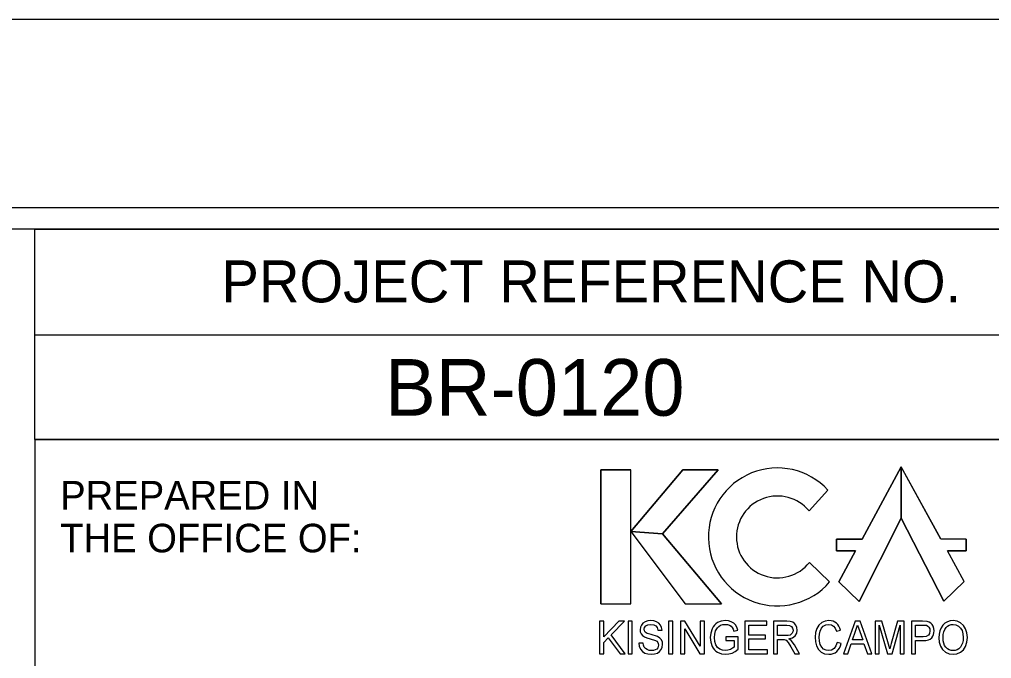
# Model space of a CAD drawing. Extents: x 406996 to 407670, y -135414 to -134930.
# Drawn here: x 407582.24 to 407628.52, y -134960.54 to -134930.09 of the extents above; entities that cross this region are included whole.
import ezdxf

# ---------------------------------------------------------------- set-up
doc = ezdxf.new("R2010")
doc.units = 0
for name, color, linetype in [('Default', 7, 'Continuous'), ('Sheet Cutting Line CELL', 7, 'Continuous'), ('Sheet Data Field CELL', 7, 'Continuous'), ('Sheet Plot Border Inside CELL', 7, 'Continuous'), ('Sheet Plot Border Outside CELL', 7, 'Continuous'), ('Sheet Summary Combination CELL', 7, 'Continuous'), ('Sheet Typical CELL', 7, 'Continuous')]:
    doc.layers.add(name, color=color, linetype=linetype)

msp = doc.modelspace()

# ---------------------------------------------------------------- linework, layer by layer
at = {"layer": 'Default'}
for p, q in [((407609.928, -134957.934), (407609.928, -134951.554)), ((407609.928, -134951.554), (407611.353, -134951.554)), ((407611.353, -134951.554), (407609.928, -134951.554)), ((407611.353, -134951.554), (407609.928, -134951.554)), ((407609.928, -134951.554), (407609.928, -134957.934)), ((407611.353, -134957.934), (407611.353, -134951.554)), ((407611.353, -134954.493), (407613.82, -134951.554)), ((407611.353, -134954.493), (407611.353, -134951.554)), ((407613.82, -134951.554), (407611.353, -134954.493)), ((407611.353, -134954.493), (407611.353, -134951.554)), ((407612.858, -134954.606), (407615.511, -134951.554)), ((407612.858, -134954.606), (407615.511, -134951.554)), ((407613.82, -134951.554), (407615.511, -134951.554)), ((407615.511, -134951.554), (407613.82, -134951.554)), ((407622.358, -134954.849), (407624.225, -134951.405)), ((407624.225, -134951.405), (407622.358, -134954.849)), ((407624.225, -134951.405), (407622.358, -134954.849)), ((407624.225, -134953.849), (407624.225, -134951.405)), ((407626.107, -134954.841), (407624.225, -134951.405)), ((407624.225, -134953.849), (407624.225, -134951.405)), ((407624.225, -134953.849), (407624.225, -134951.405)), ((407626.104, -134954.849), (407624.225, -134951.405)), ((407624.225, -134951.405), (407624.225, -134953.849)), ((407620.736, -134952.51), (407619.833, -134953.506)), ((407619.833, -134953.506), (407620.736, -134952.51)), ((407622.221, -134957.826), (407624.225, -134953.849)), ((407622.221, -134957.826), (407624.225, -134953.849)), ((407626.251, -134957.805), (407624.225, -134953.849)), ((407624.225, -134953.849), (407626.251, -134957.805)), ((407611.353, -134954.493), (407613.938, -134957.934)), ((407611.353, -134957.934), (407611.353, -134954.493)), ((407612.858, -134954.606), (407611.353, -134954.493)), ((407611.353, -134954.493), (407613.938, -134957.934)), ((407611.353, -134954.493), (407612.858, -134954.606)), ((407611.353, -134957.934), (407611.353, -134954.493)), ((407612.858, -134954.606), (407615.659, -134957.934)), ((407621.141, -134954.849), (407621.141, -134955.413)), ((407622.358, -134954.849), (407621.141, -134954.849)), ((407622.358, -134954.849), (407621.141, -134954.849)), ((407621.141, -134954.849), (407621.141, -134955.413)), ((407622.358, -134954.849), (407621.141, -134954.849)), ((407621.141, -134954.849), (407621.141, -134955.413)), ((407627.32, -134954.849), (407626.104, -134954.849)), ((407627.32, -134954.849), (407626.104, -134954.849)), ((407627.32, -134954.849), (407627.32, -134955.413)), ((407627.32, -134955.413), (407627.32, -134954.849)), ((407622.052, -134955.413), (407621.141, -134955.413)), ((407621.141, -134955.413), (407622.052, -134955.413)), ((407621.141, -134955.413), (407622.052, -134955.413)), ((407621.251, -134956.891), (407622.052, -134955.413)), ((407622.052, -134955.413), (407621.251, -134956.891)), ((407622.052, -134955.413), (407621.251, -134956.891)), ((407627.32, -134955.413), (407626.421, -134955.413)), ((407627.22, -134956.871), (407626.421, -134955.413)), ((407627.22, -134956.871), (407626.421, -134955.413)), ((407626.421, -134955.413), (407627.32, -134955.413)), ((407619.853, -134955.961), (407620.815, -134956.892)), ((407620.815, -134956.892), (407619.853, -134955.961)), ((407621.251, -134956.891), (407622.221, -134957.826)), ((407621.251, -134956.891), (407622.221, -134957.826)), ((407627.22, -134956.871), (407626.251, -134957.805)), ((407626.251, -134957.805), (407627.22, -134956.871)), ((407609.928, -134957.934), (407611.353, -134957.934)), ((407609.928, -134957.934), (407611.353, -134957.934)), ((407613.938, -134957.934), (407615.659, -134957.934))]:
    msp.add_line(p, q, dxfattribs=at)
for points in [[(407609.928, -134951.554), (407609.928, -134957.934), (407611.353, -134957.934), (407611.353, -134951.554)], [(407611.353, -134954.493), (407613.82, -134951.554), (407615.511, -134951.554), (407612.858, -134954.606)], [(407624.225, -134953.849), (407622.221, -134957.826), (407621.251, -134956.891), (407622.052, -134955.413), (407621.141, -134955.413), (407621.141, -134954.849), (407622.358, -134954.849), (407624.225, -134951.405)], [(407624.225, -134951.405), (407624.225, -134953.849), (407626.251, -134957.805), (407627.22, -134956.871), (407626.421, -134955.413), (407627.32, -134955.413), (407627.32, -134954.849), (407626.104, -134954.849)], [(407611.353, -134954.493), (407613.938, -134957.934), (407615.659, -134957.934), (407612.858, -134954.606)], [(407609.861, -134960.309), (407610.059, -134960.309), (407610.059, -134959.774), (407610.278, -134959.551), (407610.837, -134960.309), (407611.079, -134960.309), (407610.417, -134959.41), (407611.051, -134958.765), (407610.778, -134958.765), (407610.059, -134959.498), (407610.059, -134958.765), (407609.861, -134958.765)], [(407611.221, -134960.309), (407611.42, -134960.309), (407611.42, -134958.765), (407611.221, -134958.765)], [(407611.731, -134959.804), (407611.753, -134959.954), (407611.809, -134960.088), (407611.898, -134960.198), (407612.015, -134960.276), (407612.161, -134960.323), (407612.339, -134960.338), (407612.483, -134960.323), (407612.613, -134960.278), (407612.72, -134960.205), (407612.8, -134960.108), (407612.849, -134959.995), (407612.865, -134959.875), (407612.85, -134959.758), (407612.806, -134959.655), (407612.73, -134959.567), (407612.622, -134959.497), (407612.315, -134959.397), (407612.135, -134959.341), (407612.04, -134959.286), (407612, -134959.225), (407611.987, -134959.148), (407612.005, -134959.058), (407612.062, -134958.982), (407612.16, -134958.931), (407612.303, -134958.914), (407612.442, -134958.931), (407612.543, -134958.981), (407612.607, -134959.065), (407612.638, -134959.181), (407612.837, -134959.181), (407612.816, -134959.057), (407612.766, -134958.946), (407612.686, -134958.855), (407612.578, -134958.789), (407612.446, -134958.749), (407612.295, -134958.735), (407612.156, -134958.749), (407612.031, -134958.788), (407611.926, -134958.854), (407611.85, -134958.944), (407611.804, -134959.05), (407611.788, -134959.164), (407611.801, -134959.266), (407611.84, -134959.357), (407611.906, -134959.436), (407612, -134959.502), (407612.109, -134959.549), (407612.272, -134959.599), (407612.517, -134959.675), (407612.59, -134959.717), (407612.635, -134959.768), (407612.659, -134959.828), (407612.667, -134959.897), (407612.657, -134959.967), (407612.628, -134960.031), (407612.58, -134960.085), (407612.511, -134960.126), (407612.427, -134960.152), (407612.33, -134960.16), (407612.22, -134960.149), (407612.122, -134960.114), (407612.042, -134960.062), (407611.986, -134959.994), (407611.949, -134959.91), (407611.93, -134959.804)], [(407613.149, -134960.309), (407613.347, -134960.309), (407613.347, -134958.765), (407613.149, -134958.765)], [(407613.716, -134960.309), (407613.914, -134960.309), (407613.914, -134959.127), (407614.638, -134960.309), (407614.849, -134960.309), (407614.849, -134958.765), (407614.651, -134958.765), (407614.651, -134959.946), (407613.927, -134958.765), (407613.716, -134958.765)], [(407615.869, -134959.685), (407616.266, -134959.685), (407616.266, -134959.991), (407616.191, -134960.05), (407616.089, -134960.106), (407615.972, -134960.147), (407615.851, -134960.16), (407615.715, -134960.144), (407615.586, -134960.093), (407615.476, -134960.007), (407615.396, -134959.884), (407615.346, -134959.728), (407615.331, -134959.536), (407615.344, -134959.374), (407615.385, -134959.223), (407615.474, -134959.069), (407615.541, -134959.006), (407615.626, -134958.957), (407615.728, -134958.925), (407615.849, -134958.914), (407615.951, -134958.924), (407616.044, -134958.953), (407616.122, -134959), (407616.18, -134959.059), (407616.223, -134959.137), (407616.259, -134959.24), (407616.441, -134959.19), (407616.395, -134959.05), (407616.332, -134958.939), (407616.247, -134958.854), (407616.134, -134958.789), (407616.001, -134958.749), (407615.852, -134958.735), (407615.65, -134958.76), (407615.473, -134958.83), (407615.395, -134958.885), (407615.327, -134958.951), (407615.268, -134959.03), (407615.22, -134959.122), (407615.154, -134959.326), (407615.132, -134959.544), (407615.154, -134959.762), (407615.22, -134959.958), (407615.269, -134960.045), (407615.33, -134960.121), (407615.401, -134960.187), (407615.482, -134960.241), (407615.665, -134960.314), (407615.868, -134960.338), (407616.023, -134960.323), (407616.174, -134960.277), (407616.321, -134960.2), (407616.464, -134960.092), (407616.464, -134959.507), (407615.869, -134959.507)], [(407616.776, -134960.309), (407617.852, -134960.309), (407617.852, -134960.131), (407616.974, -134960.131), (407616.974, -134959.596), (407617.767, -134959.596), (407617.767, -134959.418), (407616.974, -134959.418), (407616.974, -134958.943), (407617.824, -134958.943), (407617.824, -134958.765), (407616.776, -134958.765)], [(407621.168, -134959.768), (407621.113, -134959.939), (407621.024, -134960.062), (407620.906, -134960.136), (407620.764, -134960.16), (407620.642, -134960.142), (407620.529, -134960.088), (407620.435, -134959.997), (407620.369, -134959.868), (407620.331, -134959.709), (407620.318, -134959.524), (407620.329, -134959.374), (407620.361, -134959.228), (407620.419, -134959.099), (407620.51, -134958.999), (407620.629, -134958.935), (407620.774, -134958.914), (407620.899, -134958.933), (407621.001, -134958.991), (407621.081, -134959.091), (407621.14, -134959.236), (407621.338, -134959.189), (407621.304, -134959.087), (407621.259, -134958.997), (407621.203, -134958.92), (407621.137, -134958.855), (407621.061, -134958.803), (407620.977, -134958.765), (407620.884, -134958.743), (407620.783, -134958.735), (407620.605, -134958.759), (407620.442, -134958.829), (407620.305, -134958.945), (407620.203, -134959.103), (407620.14, -134959.299), (407620.12, -134959.525), (407620.138, -134959.741), (407620.194, -134959.941), (407620.286, -134960.112), (407620.412, -134960.236), (407620.575, -134960.313), (407620.782, -134960.338), (407620.888, -134960.33), (407620.986, -134960.305), (407621.075, -134960.264), (407621.155, -134960.205), (407621.225, -134960.132), (407621.284, -134960.042), (407621.331, -134959.939), (407621.366, -134959.819)], [(407622.982, -134960.309), (407623.18, -134960.309), (407623.18, -134958.943), (407623.568, -134960.309), (407623.785, -134960.309), (407624.172, -134958.943), (407624.172, -134960.309), (407624.37, -134960.309), (407624.37, -134958.765), (407624.052, -134958.765), (407623.744, -134959.83), (407623.676, -134960.075), (407623.613, -134959.849), (407623.301, -134958.765), (407622.982, -134958.765)]]:
    msp.add_lwpolyline(points, close=True, dxfattribs=at)
for points in [[(407609.928, -134951.554), (407609.928, -134957.934), (407611.353, -134957.934)], [(407621.251, -134956.891), (407622.221, -134957.826), (407624.225, -134953.849)], [(407613.938, -134957.934), (407615.659, -134957.934), (407612.858, -134954.606)], [(407618.136, -134960.309), (407618.335, -134960.309), (407618.335, -134959.626), (407618.55, -134959.626), (407618.653, -134959.632), (407618.738, -134959.667), (407618.832, -134959.768), (407618.966, -134959.983), (407619.151, -134960.309), (407619.377, -134960.309), (407619.136, -134959.882), (407618.984, -134959.676), (407618.875, -134959.596), (407619.05, -134959.546), (407619.173, -134959.455), (407619.245, -134959.331), (407619.27, -134959.181), (407619.255, -134959.061), (407619.211, -134958.952), (407619.143, -134958.864), (407619.055, -134958.806), (407618.935, -134958.776), (407618.771, -134958.765), (407618.136, -134958.765), (407618.136, -134960.309)], [(407618.335, -134959.448), (407618.335, -134958.943), (407618.778, -134958.943), (407618.91, -134958.961), (407619.001, -134959.013), (407619.054, -134959.093), (407619.071, -134959.191), (407619.062, -134959.262), (407619.035, -134959.328), (407618.99, -134959.383), (407618.93, -134959.42), (407618.846, -134959.441), (407618.734, -134959.448), (407618.335, -134959.448)], [(407621.469, -134960.309), (407621.678, -134960.309), (407621.841, -134959.834), (407622.45, -134959.834), (407622.613, -134960.309), (407622.822, -134960.309), (407622.263, -134958.765), (407622.028, -134958.765), (407621.469, -134960.309)], [(407621.901, -134959.656), (407622.048, -134959.228), (407622.146, -134958.943), (407622.251, -134959.253), (407622.39, -134959.656), (407621.901, -134959.656)], [(407624.709, -134960.309), (407624.908, -134960.309), (407624.908, -134959.685), (407625.265, -134959.685), (407625.401, -134959.677), (407625.515, -134959.652), (407625.605, -134959.609), (407625.673, -134959.549), (407625.723, -134959.476), (407625.758, -134959.396), (407625.779, -134959.309), (407625.786, -134959.214), (407625.775, -134959.103), (407625.743, -134959.002), (407625.694, -134958.917), (407625.631, -134958.852), (407625.552, -134958.808), (407625.457, -134958.78), (407625.242, -134958.765), (407624.709, -134958.765), (407624.709, -134960.309)], [(407624.908, -134959.507), (407624.908, -134958.943), (407625.26, -134958.943), (407625.43, -134958.957), (407625.494, -134958.992), (407625.544, -134959.05), (407625.577, -134959.128), (407625.588, -134959.22), (407625.569, -134959.342), (407625.514, -134959.432), (407625.414, -134959.489), (407625.264, -134959.507), (407624.908, -134959.507)], [(407626.013, -134959.557), (407626.034, -134959.756), (407626.095, -134959.944), (407626.195, -134960.108), (407626.335, -134960.233), (407626.503, -134960.312), (407626.694, -134960.338), (407626.873, -134960.315), (407627.039, -134960.243), (407627.181, -134960.125), (407627.286, -134959.961), (407627.351, -134959.763), (407627.374, -134959.54), (407627.353, -134959.319), (407627.29, -134959.124), (407627.189, -134958.961), (407627.05, -134958.838), (407626.881, -134958.761), (407626.695, -134958.735), (407626.551, -134958.749), (407626.421, -134958.79), (407626.305, -134958.859), (407626.203, -134958.954), (407626.12, -134959.074), (407626.061, -134959.214), (407626.025, -134959.376), (407626.013, -134959.557)], [(407626.212, -134959.56), (407626.221, -134959.398), (407626.247, -134959.261), (407626.292, -134959.15), (407626.354, -134959.062), (407626.429, -134958.997), (407626.511, -134958.951), (407626.599, -134958.923), (407626.695, -134958.914), (407626.828, -134958.933), (407626.947, -134958.991), (407627.045, -134959.085), (407627.117, -134959.209), (407627.161, -134959.362), (407627.175, -134959.538), (407627.166, -134959.679), (407627.141, -134959.802), (407627.098, -134959.909), (407627.039, -134959.998), (407626.966, -134960.07), (407626.884, -134960.12), (407626.793, -134960.151), (407626.693, -134960.16), (407626.594, -134960.151), (407626.503, -134960.12), (407626.421, -134960.07), (407626.349, -134960), (407626.288, -134959.913), (407626.246, -134959.81), (407626.22, -134959.693), (407626.212, -134959.56)]]:
    msp.add_lwpolyline(points, dxfattribs=at)
for radius, start, end in [(3.285, 42.8783, 319.2064), (3.285, 42.8783, 319.2064), (1.95, 39.4666, 321.4328), (1.95, 39.4666, 321.4328)]:
    msp.add_arc((407618.328, -134954.746), radius, start, end, dxfattribs=at)
at = {"layer": 'Sheet Cutting Line CELL'}
msp.add_line((407669.8, -134930.091), (406996.2, -134930.091), dxfattribs=at)
at = {"layer": 'Sheet Plot Border Inside CELL'}
msp.add_lwpolyline([(407668, -134939.071), (407001.4, -134939.071), (407001.4, -135361.111), (407668, -135361.111)], close=True, dxfattribs=at)
at = {"layer": 'Sheet Plot Border Outside CELL'}
msp.add_lwpolyline([(407669.8, -134930.091), (406996.2, -134930.091), (406996.2, -135370.091), (407669.8, -135370.091)], close=True, dxfattribs=at)
at = {"layer": 'Sheet Summary Combination CELL'}
for p, q in [((407582.98, -134945.111), (407663, -134945.111)), ((407582.98, -134950.111), (407663, -134950.111))]:
    msp.add_line(p, q, dxfattribs=at)
for points in [[(407663, -134940.091), (407063, -134940.091), (407063, -135360.091), (407663, -135360.091)], [(407582.98, -134940.091), (407663, -134940.091), (407663, -134950.111), (407582.98, -134950.111)]]:
    msp.add_lwpolyline(points, close=True, dxfattribs=at)
at = {"layer": 'Sheet Typical CELL'}
msp.add_lwpolyline([(407662.995, -134950.111), (407582.98, -134950.111), (407582.98, -134964.182), (407662.995, -134964.182)], close=True, dxfattribs=at)

# ---------------------------------------------------------------- texts
at = {"layer": 'Default'}
for s, p in [('PREPARED IN ', (407584.183, -134953.439)), ('THE OFFICE OF:', (407584.183, -134955.479))]:
    msp.add_text(s, height=1.36, rotation=360, dxfattribs=at).set_placement(p)
at = {"layer": 'Sheet Data Field CELL'}
msp.add_text('BR-0120', height=2.7, dxfattribs=at).set_placement((407599.654, -134948.971))
at = {"layer": 'Sheet Summary Combination CELL'}
msp.add_text('PROJECT REFERENCE NO.', height=2.00004, dxfattribs=at).set_placement((407591.86, -134943.571))

doc.saveas('drawing.dxf')
